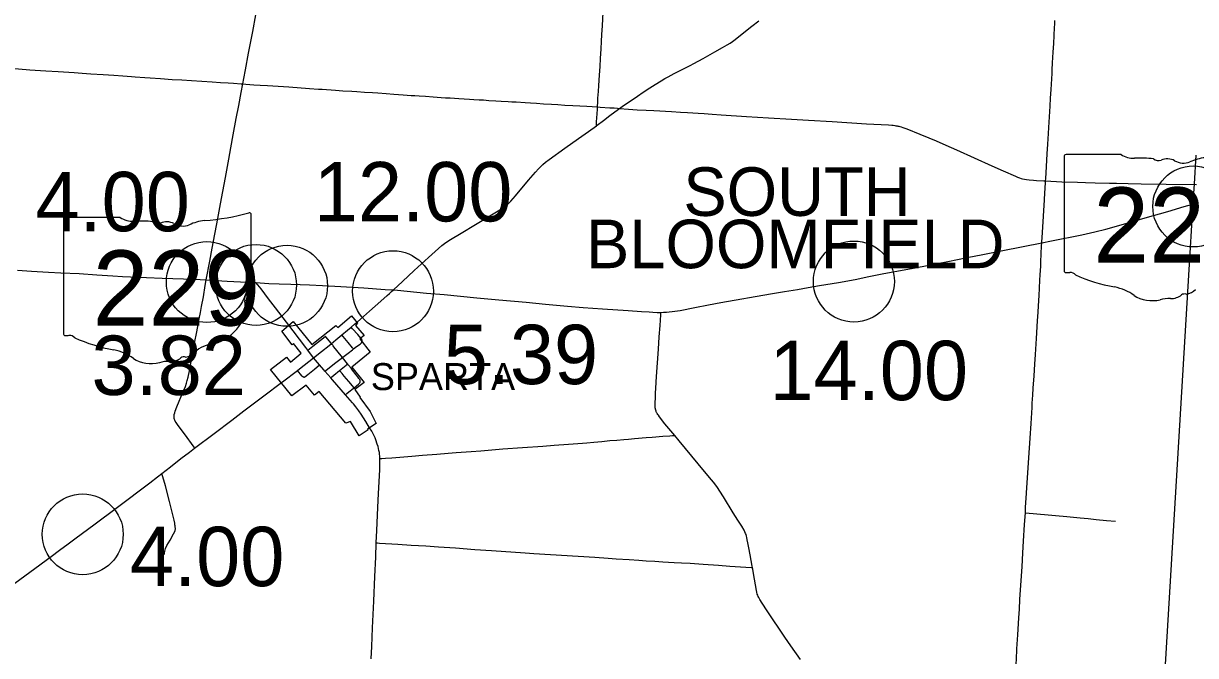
# Model space of a CAD drawing. Extents: x 1813937 to 1948437, y 826606 to 1022856.
# Drawn here: x 1907255 to 1928982, y 866833 to 878544 of the extents above; entities that cross this region are included whole.
import ezdxf

# ---------------------------------------------------------------- set-up
doc = ezdxf.new("R2010")
doc.units = 0
for name, color, linetype in [('Default', 7, 'Continuous'), ('GM_X_City_Street', 7, 'Continuous'), ('GM_X_Corporation', 7, 'Continuous'), ('GM_X_Corporation_Text', 7, 'Continuous'), ('GM_X_County', 7, 'Continuous'), ('GM_X_County_Road', 7, 'Continuous'), ('GM_X_State_Route', 7, 'Continuous'), ('GM_X_State_Shield', 7, 'Continuous'), ('GM_X_Township_Road', 7, 'Continuous'), ('GM_X_Township_Text', 7, 'Continuous')]:
    doc.layers.add(name, color=color, linetype=linetype)

msp = doc.modelspace()

# ---------------------------------------------------------------- linework, layer by layer
at = {"layer": 'Default'}
for centre in [(1928940, 875154), (1910654, 873753), (1911566, 873699), (1912141, 873684), (1914105, 873583), (1922649, 873763), (1908353, 869079)]:
    msp.add_circle(centre, 750, dxfattribs=at)
at = {"layer": 'GM_X_City_Street'}
for points in [[(1913534, 872652), (1913534, 872655), (1913534, 872657), (1913534, 872659), (1913534, 872660), (1913534, 872662), (1913534, 872665), (1913533, 872671), (1913532, 872677), (1913530, 872681), (1913528, 872687), (1913526, 872690), (1913525, 872693), (1913522, 872699), (1913516, 872706), (1913510, 872715), (1913451, 872780), (1913356, 872886), (1913328, 872917)], [(1912525, 872493), (1912622, 872568), (1912846, 872742), (1912847, 872743), (1912848, 872744), (1912849, 872744), (1912850, 872744), (1912851, 872745), (1912852, 872745), (1912855, 872745)], [(1912960, 872610), (1912950, 872624), (1912867, 872732), (1912861, 872740), (1912861, 872741), (1912860, 872741), (1912858, 872743), (1912858, 872743), (1912857, 872744), (1912855, 872745)], [(1913168, 872356), (1913142, 872389), (1913010, 872554), (1912997, 872571), (1912988, 872581), (1912981, 872589), (1912972, 872599), (1912960, 872610)], [(1913372, 872513), (1913357, 872532), (1913276, 872632), (1913183, 872744), (1913158, 872773)], [(1913372, 872513), (1913431, 872556), (1913496, 872605), (1913513, 872620), (1913517, 872624), (1913522, 872629), (1913525, 872634), (1913529, 872641), (1913530, 872644), (1913531, 872646), (1913532, 872648), (1913533, 872651), (1913534, 872652)], [(1913168, 872356), (1913173, 872360), (1913275, 872438), (1913352, 872498), (1913372, 872513)], [(1912453, 871991), (1912456, 871991), (1912459, 871991), (1912462, 871992), (1912465, 871992), (1912466, 871992), (1912467, 871993), (1912469, 871994), (1912470, 871995), (1912471, 871996), (1912473, 871997), (1912526, 872041), (1912647, 872140), (1912742, 872221)], [(1912843, 872105), (1912864, 872121), (1913045, 872260), (1913168, 872356)], [(1913114, 872113), (1913238, 872213), (1913263, 872235)], [(1913263, 872235), (1913168, 872356)], [(1913494, 871894), (1913496, 871899), (1913497, 871905), (1913497, 871911), (1913497, 871918), (1913496, 871928), (1913494, 871935), (1913492, 871941), (1913489, 871947), (1913484, 871956), (1913474, 871969), (1913451, 872000), (1913424, 872034), (1913353, 872122), (1913328, 872155), (1913283, 872211), (1913263, 872235)], [(1912453, 871991), (1912449, 871991), (1912446, 871992), (1912443, 871993), (1912441, 871994), (1912438, 871995), (1912436, 871996), (1912434, 871997), (1912430, 872000), (1912426, 872003), (1912421, 872009), (1912417, 872012), (1912413, 872017), (1912388, 872046), (1912357, 872085), (1912333, 872117)], [(1912952, 871981), (1912972, 871998), (1913010, 872029), (1913114, 872113)], [(1913384, 871796), (1913287, 871910), (1913199, 872009), (1913160, 872057), (1913114, 872113)], [(1913225, 871666), (1913252, 871688), (1913289, 871719), (1913313, 871740), (1913340, 871762), (1913384, 871796)], [(1913384, 871796), (1913466, 871859), (1913486, 871878), (1913491, 871885), (1913492, 871889), (1913494, 871894)]]:
    msp.add_lwpolyline(points, dxfattribs=at)
at = {"layer": 'GM_X_Corporation'}
msp.add_lwpolyline([(1913233, 871137), (1912739, 871727), (1912650, 871656), (1912497, 871840), (1912228, 871646), (1911837, 872131), (1912128, 872361), (1912202, 872267), (1912400, 872433), (1912262, 872613), (1912235, 872592), (1912045, 872846), (1912253, 873024), (1912601, 872595), (1913046, 872947), (1913082, 872913), (1913338, 873127), (1913450, 872989), (1913407, 872950), (1913568, 872762), (1913491, 872701), (1913680, 872455), (1913345, 872174), (1913569, 871895), (1913400, 871760), (1913496, 871622), (1913488, 871616), (1913679, 871355), (1913791, 871135), (1913633, 871028), (1913642, 871016), (1913476, 870904), (1913318, 871168)], close=True, dxfattribs=at)
at = {"layer": 'GM_X_County'}
msp.add_lwpolyline([(1928987, 876105), (1928954, 875572), (1928932, 875213), (1928849, 873883), (1928341, 865325), (1928314, 865105), (1928189, 862861), (1927988, 859624), (1927907, 858279), (1927777, 856135), (1927658, 854184), (1924873, 854361), (1922111, 854537), (1916549, 854893), (1915609, 854967), (1909640, 855342), (1905546, 855583)], dxfattribs=at)
at = {"layer": 'GM_X_County_Road'}
for points in [[(1918304, 876971), (1918377, 877023), (1918541, 877132), (1918636, 877196), (1918745, 877270), (1918868, 877350), (1918965, 877411), (1919076, 877481), (1919146, 877523), (1919204, 877554), (1919320, 877615), (1919378, 877645), (1919480, 877698), (1919611, 877765), (1919684, 877804), (1919857, 877898), (1919943, 877945), (1920072, 878017), (1920215, 878096), (1920300, 878146), (1920356, 878182), (1920396, 878210), (1920448, 878250), (1920641, 878401), (1920758, 878492), (1920888, 878591)], [(1926202, 875626), (1926204, 875668), (1926219, 875897), (1926234, 876127), (1926245, 876307), (1926257, 876503), (1926264, 876618), (1926275, 876814), (1926287, 877011), (1926296, 877158), (1926305, 877322), (1926322, 877617), (1926325, 877682), (1926332, 877813), (1926343, 878010), (1926352, 878174), (1926362, 878321), (1926370, 878468), (1926373, 878534), (1926376, 878599)], [(1917877, 876650), (1917891, 876661), (1918009, 876749), (1918126, 876839), (1918284, 876956), (1918304, 876971)], [(1918304, 876971), (1918468, 876957), (1918631, 876947), (1918795, 876938), (1918942, 876930), (1919269, 876912), (1919433, 876901), (1919564, 876892), (1919760, 876880), (1919875, 876874), (1920022, 876864), (1920186, 876854), (1920660, 876823), (1921068, 876797), (1921493, 876773), (1921805, 876753), (1922247, 876726), (1922884, 876687), (1923293, 876663), (1923353, 876660), (1923377, 876658), (1923408, 876653), (1923428, 876650), (1923451, 876647), (1923464, 876644), (1923482, 876640), (1923501, 876635), (1923522, 876629), (1923554, 876619), (1923628, 876592), (1923871, 876492), (1924037, 876423), (1924173, 876367), (1924354, 876288), (1924549, 876201), (1925207, 875906), (1925417, 875812), (1925642, 875712), (1925681, 875696), (1925719, 875683), (1925749, 875674), (1925775, 875667), (1925809, 875660), (1925846, 875653), (1925897, 875647), (1925977, 875639), (1926031, 875634), (1926169, 875628), (1926202, 875626)], [(1914112, 873607), (1914282, 873766), (1914500, 873965), (1914632, 874088), (1914825, 874266), (1914947, 874375), (1915010, 874428), (1915061, 874468), (1915101, 874496), (1915170, 874540), (1915366, 874660), (1915633, 874821), (1916057, 875070), (1916127, 875113), (1916168, 875141), (1916207, 875171), (1916243, 875205), (1916288, 875253), (1916374, 875353), (1916619, 875640), (1916747, 875789), (1916801, 875850), (1916846, 875897), (1916882, 875930), (1916932, 875972), (1916997, 876022), (1917291, 876232), (1917545, 876411), (1917732, 876545), (1917877, 876650)], [(1926131, 874480), (1926131, 874490), (1926142, 874670), (1926181, 875276), (1926189, 875407), (1926194, 875489), (1926200, 875603), (1926202, 875626)], [(1926202, 875626), (1926501, 875612), (1926796, 875602), (1926944, 875599), (1927124, 875594), (1927387, 875587), (1927518, 875584), (1927731, 875579), (1927976, 875573), (1928436, 875567), (1928999, 875559)], [(1925827, 869476), (1925832, 869582), (1925842, 869746), (1925854, 869943), (1925889, 870499), (1925914, 870859), (1925932, 871135), (1925951, 871429), (1925956, 871510), (1925965, 871658), (1925974, 871788), (1925990, 872018), (1926005, 872230), (1926015, 872411), (1926021, 872509), (1926032, 872705), (1926051, 873033), (1926062, 873196), (1926069, 873311), (1926081, 873507), (1926089, 873638), (1926097, 873786), (1926103, 873884), (1926111, 874047), (1926115, 874129), (1926123, 874277), (1926129, 874424), (1926131, 874480)], [(1925577, 865482), (1925590, 865650), (1925613, 866026), (1925635, 866353), (1925651, 866614), (1925660, 866761), (1925672, 866958), (1925687, 867219), (1925706, 867530), (1925716, 867693), (1925727, 867873), (1925743, 868135), (1925765, 868478), (1925780, 868739), (1925793, 868952), (1925813, 869262), (1925827, 869476)]]:
    msp.add_lwpolyline(points, dxfattribs=at)
at = {"layer": 'GM_X_State_Route'}
for points in [[(1910643, 873793), (1910707, 874140), (1910753, 874381), (1910856, 874930), (1910907, 875204), (1910949, 875430), (1910998, 875688), (1911060, 876027), (1911100, 876237), (1911144, 876479), (1911200, 876785), (1911246, 877026), (1911292, 877268), (1911321, 877425), (1911339, 877526), (1911369, 877687), (1911428, 877994), (1911506, 878396), (1911563, 878703)], [(1914112, 873607), (1914188, 873602), (1914727, 873549), (1915054, 873520), (1915657, 873463), (1916065, 873425), (1916572, 873378), (1916930, 873345), (1917338, 873308), (1917632, 873282), (1917990, 873255), (1918465, 873224), (1918710, 873208), (1918852, 873199), (1918922, 873195), (1919001, 873192), (1919070, 873191), (1919121, 873193), (1919172, 873194), (1919226, 873199), (1919282, 873205), (1919428, 873229), (1919698, 873284), (1919956, 873334), (1920182, 873374), (1921104, 873533), (1921362, 873577), (1921605, 873617), (1921799, 873650), (1922009, 873687), (1922365, 873747), (1922671, 873803), (1922928, 873856), (1923202, 873911), (1923783, 874016), (1924201, 874098), (1924393, 874136), (1924750, 874207), (1925038, 874265), (1925408, 874339), (1926131, 874480), (1926311, 874516), (1926872, 874630), (1927112, 874685), (1927319, 874736), (1927604, 874814), (1928045, 874940), (1928471, 875062), (1928769, 875150), (1928977, 875210)], [(1907143, 873972), (1907404, 873956), (1907716, 873938), (1907945, 873925), (1908289, 873909), (1908616, 873889), (1908911, 873869), (1909091, 873858), (1909238, 873850), (1909533, 873839), (1909828, 873828), (1910419, 873804), (1910643, 873793)], [(1910643, 873793), (1911029, 873772), (1911523, 873744), (1911561, 873742)], [(1911561, 873742), (1911801, 873729), (1911998, 873721), (1912211, 873713), (1912555, 873700), (1912799, 873688), (1913141, 873670), (1913566, 873644), (1913959, 873618), (1914112, 873607)], [(1912172, 872953), (1912128, 873011), (1911930, 873273), (1911800, 873443), (1911660, 873625), (1911597, 873701), (1911561, 873742)], [(1913438, 873010), (1913558, 873116), (1913668, 873215), (1913880, 873400), (1913999, 873504), (1914042, 873542), (1914078, 873576), (1914112, 873607)], [(1912037, 871890), (1912059, 871906), (1912333, 872117), (1912369, 872145), (1912634, 872350), (1912779, 872464), (1912920, 872577), (1912960, 872610), (1913048, 872680), (1913158, 872773), (1913262, 872859), (1913328, 872917), (1913394, 872974)], [(1913370, 871497), (1913357, 871513), (1913225, 871666), (1912984, 871944), (1912952, 871981), (1912843, 872105), (1912823, 872127), (1912742, 872221), (1912634, 872350), (1912525, 872493), (1912491, 872539), (1912254, 872850), (1912172, 872953)], [(1913394, 872974), (1913438, 873010)], [(1907094, 868173), (1907371, 868378), (1907767, 868670), (1907925, 868788), (1908084, 868904), (1908229, 869012), (1908560, 869258), (1908996, 869580), (1909598, 870031), (1909740, 870142), (1909822, 870205), (1909980, 870331), (1910174, 870483), (1910330, 870603), (1910428, 870676), (1910790, 870948), (1911118, 871196), (1911340, 871366), (1911708, 871642), (1912037, 871890)], [(1913672, 871054), (1913601, 871170), (1913513, 871303), (1913471, 871366), (1913415, 871442), (1913370, 871497)], [(1913699, 866773), (1913710, 867002), (1913725, 867346), (1913749, 867838), (1913769, 868296), (1913784, 868657), (1913796, 868921), (1913807, 869148), (1913827, 869574), (1913837, 869836), (1913858, 870277), (1913862, 870354), (1913862, 870407), (1913864, 870466), (1913864, 870483), (1913864, 870489), (1913863, 870507), (1913861, 870532), (1913857, 870560), (1913852, 870595), (1913845, 870631), (1913837, 870668), (1913828, 870704), (1913814, 870751), (1913788, 870829), (1913772, 870867), (1913755, 870904), (1913731, 870951), (1913710, 870992), (1913672, 871054)]]:
    msp.add_lwpolyline(points, dxfattribs=at)
at = {"layer": 'GM_X_State_Shield'}
for p, q in [((1926547, 876077), (1926547, 873964)), ((1927601, 876114), (1926581, 876114)), ((1911477, 873895), (1911477, 875000)), ((1907997, 874911), (1907997, 872798)), ((1909050, 874948), (1908031, 874948)), ((1911477, 873895), (1911477, 873895))]:
    msp.add_line(p, q, dxfattribs=at)
for centre, major_axis, start_param, end_param in [((1926587, 876082), (40.3, 0), 1.712693, 3.28349), ((1927843, 876359), (391, 0), 4.042523, 4.731795), ((1929258, 875468), (743, 0), 1.699011, 2.107814), ((1927973, 874927), (1404, 0), 1.404758, 1.657858), ((1928292, 876093), (113, 0), 3.836095, 5.185415), ((1928457, 875848), (235, 0), 0.950623, 2.079405), ((1928760, 876183), (282, 0), 4.081561, 5.145723), ((1910237, 877829), (3691, 0), 4.814394, 5.042369), ((1911438, 875005), (38.7, 0), 6.141152, 7.989035), ((1908037, 874916), (40.3, 0), 1.712693, 3.28349), ((1909293, 875193), (391, 0), 4.042523, 4.731795), ((1909423, 873761), (1404, 0), 1.404758, 1.657858), ((1909741, 874927), (113, 0), 3.836095, 5.185415), ((1909907, 874682), (235, 0), 0.950623, 2.079405), ((1910210, 875017), (282, 0), 4.081561, 5.145723), ((1910708, 874302), (743, 0), 1.699011, 2.107814), ((1911436, 873890), (41.5, 0), 5.05454, 6.418171), ((1926587, 873959), (40.7, 0), 3.00124, 4.508301), ((1926593, 874176), (310, 0), 4.665946, 4.897461), ((1926657, 873842), (112, 0), 0.519207, 1.627899), ((1928070, 875741), (2665, 0), 4.195997, 4.488961), ((1911468, 873813), (60, 0), 1.883978, 3.671073), ((1911087, 873674), (360, 0), 5.934695, 6.695948), ((1911616, 873432), (262, 0), 2.387724, 3.262537), ((1927276, 873015), (834, 0), 0.823519, 1.323587), ((1928177, 873832), (529, 0), 4.026481, 4.996735), ((1928483, 873101), (435, 0), 1.495662, 1.94098), ((1928522, 873673), (282, 0), 4.691044, 5.507374), ((1928777, 873469), (79.4, 0), 1.147584, 2.315152), ((1928743, 873759), (298, 0), 4.937069, 5.64225), ((1910444, 873291), (923, 0), 5.101752, 6.440018), ((1908037, 872793), (40.7, 0), 3.00124, 4.508301), ((1908043, 873010), (310, 0), 4.665946, 4.897461), ((1908107, 872676), (112, 0), 0.519207, 1.627899), ((1909520, 874575), (2665, 0), 4.195997, 4.488961), ((1910833, 872205), (506, 0), 1.647645, 2.488434), ((1908725, 871849), (834, 0), 0.823519, 1.323587), ((1910227, 872303), (79.4, 0), 1.147584, 2.315152), ((1910193, 872593), (298, 0), 4.937069, 5.64225), ((1909627, 872666), (529, 0), 4.026481, 4.996735), ((1909933, 871935), (435, 0), 1.495662, 1.94098), ((1909972, 872507), (282, 0), 4.691044, 5.507374)]:
    msp.add_ellipse(centre, major_axis=major_axis, ratio=0.8, start_param=start_param, end_param=end_param, dxfattribs=at)
at = {"layer": 'GM_X_Township_Road'}
for points in [[(1917894, 876997), (1917901, 877093), (1917905, 877158), (1917914, 877281), (1917922, 877392), (1917933, 877584), (1917943, 877748), (1917952, 877895), (1917961, 878075), (1917968, 878207), (1917976, 878338), (1917988, 878501), (1918002, 878754)], [(1906935, 877716), (1907164, 877701), (1907376, 877688), (1907671, 877669), (1907900, 877654), (1908195, 877633), (1908342, 877624)], [(1908342, 877624), (1908506, 877614), (1908735, 877597), (1908931, 877584), (1909095, 877572), (1909259, 877562), (1909324, 877557), (1909504, 877543), (1909602, 877536), (1909798, 877523), (1910011, 877508), (1910190, 877497), (1910369, 877485), (1910755, 877460), (1910905, 877450), (1911049, 877442), (1911147, 877435), (1911290, 877427), (1911321, 877425)], [(1911321, 877425), (1911378, 877422), (1911527, 877410), (1911644, 877404), (1911780, 877395), (1912174, 877368), (1912559, 877340), (1912722, 877329), (1912792, 877324), (1913038, 877308), (1913175, 877299), (1913340, 877289), (1913433, 877283), (1913577, 877273), (1913725, 877263), (1913826, 877256), (1913977, 877245), (1914120, 877235), (1914292, 877222), (1914443, 877212), (1914508, 877208), (1914590, 877203), (1914705, 877195), (1914852, 877185), (1914999, 877175), (1915081, 877169), (1915162, 877165), (1915326, 877154), (1915522, 877142), (1915604, 877137), (1915702, 877132), (1915784, 877127), (1915882, 877119), (1916013, 877110), (1916112, 877105), (1916243, 877098), (1916308, 877094), (1916390, 877090), (1916553, 877080), (1916651, 877073), (1916766, 877065), (1916897, 877057), (1917044, 877048), (1917158, 877040), (1917289, 877030), (1917437, 877022), (1917699, 877009), (1917894, 876997)], [(1917877, 876650), (1917878, 876686), (1917880, 876719), (1917888, 876867), (1917893, 876955), (1917894, 876994), (1917894, 876997)], [(1917894, 876997), (1917944, 876994), (1918125, 876982), (1918202, 876978), (1918264, 876974), (1918304, 876971)], [(1910428, 870676), (1910417, 870691), (1910238, 870939), (1910121, 871096), (1910084, 871150), (1910067, 871178), (1910060, 871192), (1910054, 871207), (1910050, 871222), (1910047, 871237), (1910046, 871253), (1910046, 871269), (1910048, 871285), (1910051, 871301), (1910059, 871333), (1910069, 871364), (1910097, 871440), (1910142, 871546), (1910206, 871697), (1910256, 871819), (1910278, 871881), (1910292, 871929), (1910307, 871993), (1910330, 872106), (1910367, 872317), (1910387, 872430), (1910425, 872623), (1910466, 872833), (1910513, 873073), (1910535, 873188), (1910557, 873300), (1910590, 873478), (1910625, 873688), (1910643, 873793)], [(1919327, 870913), (1919147, 871128), (1919046, 871257), (1919026, 871285), (1919015, 871300), (1919002, 871320), (1918997, 871329), (1918992, 871339), (1918986, 871351), (1918982, 871363), (1918976, 871380), (1918971, 871395), (1918968, 871410), (1918966, 871419), (1918965, 871428), (1918964, 871436), (1918963, 871446), (1918963, 871459), (1918964, 871479), (1918964, 871499), (1918965, 871534), (1918968, 871587), (1918973, 871693), (1918979, 871786), (1918992, 872001), (1919027, 872508), (1919042, 872736), (1919057, 872949), (1919069, 873145), (1919070, 873191)], [(1913864, 870483), (1913901, 870486), (1913966, 870490), (1914081, 870499), (1914457, 870529), (1914654, 870545), (1914916, 870565), (1915129, 870583), (1915276, 870594), (1915555, 870616), (1915735, 870628), (1916144, 870660), (1916505, 870686), (1916882, 870713), (1917095, 870729), (1917357, 870750), (1917619, 870770), (1917701, 870776), (1917831, 870788), (1917978, 870802), (1918126, 870815), (1918257, 870825), (1918381, 870835), (1918469, 870843), (1918584, 870853), (1918797, 870872), (1918911, 870880), (1919108, 870895), (1919239, 870904), (1919288, 870909), (1919327, 870913)], [(1920770, 868466), (1920766, 868489), (1920727, 868698), (1920702, 868827), (1920684, 868924), (1920672, 868980), (1920663, 869022), (1920657, 869046), (1920650, 869073), (1920642, 869097), (1920630, 869123), (1920612, 869159), (1920571, 869230), (1920498, 869339), (1920410, 869477), (1920230, 869771), (1920105, 869964), (1920048, 870044), (1919975, 870133), (1919764, 870383), (1919410, 870814), (1919327, 870913)], [(1909868, 868703), (1909869, 868736), (1909873, 868768), (1909887, 868815), (1909915, 868874), (1909972, 868973), (1910038, 869087), (1910059, 869131), (1910063, 869140), (1910066, 869146), (1910067, 869152), (1910069, 869159), (1910070, 869164), (1910071, 869172), (1910072, 869181), (1910072, 869188), (1910071, 869194), (1910070, 869203), (1910069, 869215), (1910066, 869234), (1910063, 869255), (1910058, 869286), (1910047, 869341), (1909959, 869690), (1909885, 869976), (1909822, 870205)], [(1925827, 869476), (1926253, 869438), (1926384, 869426), (1926597, 869408), (1926842, 869385), (1926990, 869370), (1927137, 869356), (1927333, 869338), (1927497, 869323)], [(1913796, 868921), (1913819, 868920), (1913856, 868918), (1914196, 868898), (1914441, 868881), (1914711, 868865), (1914950, 868848), (1915263, 868826), (1915622, 868800), (1915933, 868778), (1916555, 868736), (1916718, 868726), (1917848, 868654), (1918093, 868639), (1918240, 868628), (1918485, 868612), (1918665, 868599), (1918796, 868591), (1918960, 868581), (1919107, 868571), (1919320, 868559), (1919451, 868553), (1919614, 868543), (1919855, 868526), (1920138, 868506), (1920350, 868491), (1920645, 868472), (1920747, 868467), (1920770, 868466)], [(1921656, 866757), (1921478, 867013), (1921367, 867175), (1921039, 867662), (1920947, 867803), (1920905, 867871), (1920886, 867906), (1920874, 867929), (1920865, 867952), (1920858, 867972), (1920848, 868005), (1920842, 868037), (1920807, 868247), (1920770, 868466)]]:
    msp.add_lwpolyline(points, dxfattribs=at)

# ---------------------------------------------------------------- texts
at = {"layer": 'Default'}
for s, p in [('12.00', (1912637, 874877)), ('4.00', (1907477, 874694)), ('5.39', (1915045, 871862)), ('3.82', (1908516, 871661)), ('14.00', (1921084, 871565)), ('4.00', (1909229, 868119))]:
    msp.add_text(s, height=1100, dxfattribs=at).set_placement(p)
at = {"layer": 'GM_X_Corporation_Text'}
msp.add_text('SPARTA', height=500, rotation=0, dxfattribs=at).set_placement((1913694, 871751))
at = {"layer": 'GM_X_State_Shield'}
for p in [(1927087, 874113), (1908537, 872947)]:
    msp.add_text('229', height=1392.2, dxfattribs=at).set_placement(p)
at = {"layer": 'GM_X_Township_Text'}
for s, p in [('SOUTH', (1919487, 874979)), ('BLOOMFIELD', (1917683, 874010))]:
    msp.add_text(s, height=900, rotation=0, dxfattribs=at).set_placement(p)

doc.saveas('drawing.dxf')
